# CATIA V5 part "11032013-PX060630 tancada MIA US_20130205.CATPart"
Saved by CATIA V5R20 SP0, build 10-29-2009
Part number: 11032013-PX060630 tancada MIA US_20130205
Revision: ANY
Definition: UNKNOWN
Nomenclature: 11032013-PX060630 tancada MIA US_20130205
Source: Unknown
Bounding box of the stored display mesh (mm): x 0 to 175, y -10 to 0, z -6.2 to 0
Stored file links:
  C:\Users\Utente\Desktop\IO LAVORO\3D X SITO CF\CUMSA\3D files CX.013058\CX 013058\11032013-PX060630 tancada MIA US_20130205.CATPart
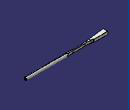
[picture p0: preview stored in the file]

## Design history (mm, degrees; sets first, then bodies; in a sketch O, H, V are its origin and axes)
Body1 "Chaflán3" (main body)
  Solid1: solid without history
